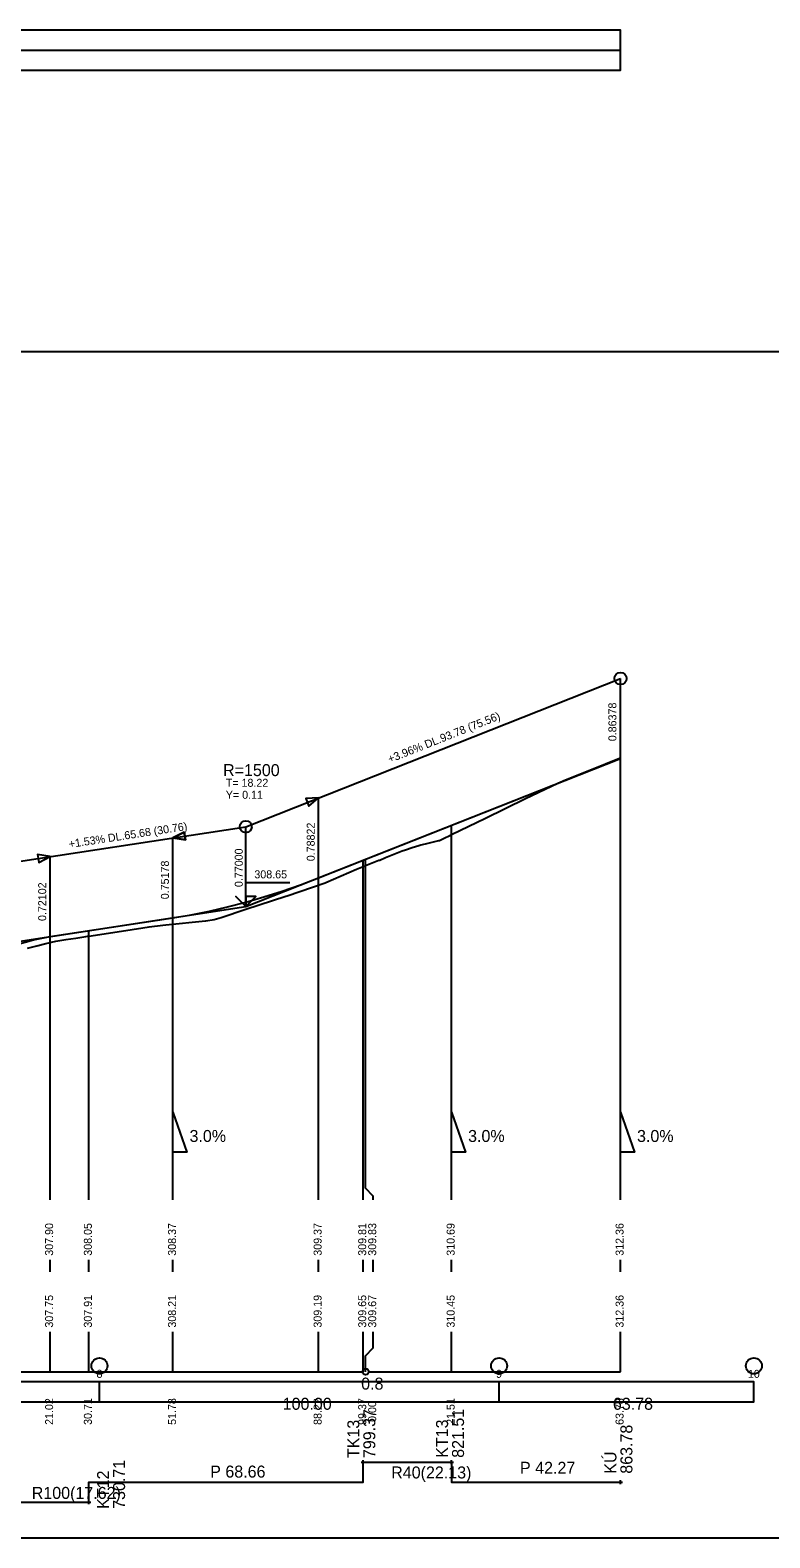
# Model space of a CAD drawing. Extents: x 999 to 1126, y 126 to 164.
# Drawn here: x 1085.78 to 1104.29, y 126.11 to 163.87 of the extents above; entities that cross this region are included whole.
import ezdxf

# ---------------------------------------------------------------- set-up
doc = ezdxf.new("R2010")
doc.units = 0
for name, color, linetype in [('KOTA', 7, 'Continuous'), ('NOVY_STAV', 7, 'Continuous'), ('NS_OBLOUK', 7, 'Continuous'), ('REZY_PO', 7, 'Continuous'), ('SESTAVY_REZU_PO', 7, 'Continuous'), ('SKLONOVE_POMERY', 7, 'Continuous'), ('SMEROVE_POMERY', 7, 'Continuous'), ('SMEROVE_POMERY_KOD', 7, 'Continuous'), ('SVK_STAT', 7, 'Continuous'), ('TABULKY', 7, 'Continuous'), ('u_pricne_rezy', 7, 'Continuous'), ('x_formát_rám', 7, 'Continuous')]:
    doc.layers.add(name, color=color, linetype=linetype)

msp = doc.modelspace()

# ---------------------------------------------------------------- linework, layer by layer
at = {"layer": 'KOTA'}
for points in [[(1091.178, 141.92), (1090.928, 142.17), (1091.178, 141.92), (1091.178, 142.52), (1092.278, 142.52)], [(1091.178, 142.17), (1091.178, 141.92), (1091.428, 142.17), (1091.178, 142.17)], [(1091.178, 141.92), (1091.428, 142.17), (1091.178, 142.17)], [(1091.178, 141.92), (1091.178, 141.92)]]:
    msp.add_lwpolyline(points, dxfattribs=at)
at = {"layer": 'NOVY_STAV'}
for points in [[(1091.178, 143.92), (1100.556, 147.632)], [(1100.556, 145.632), (1100.556, 147.632)], [(1084.178, 140.561), (1084.61, 140.916), (1091.178, 141.92), (1100.556, 145.632)], [(1084.178, 140.408), (1084.193, 140.417), (1084.61, 140.637), (1085.027, 140.823), (1085.445, 140.974), (1085.862, 141.09), (1086.28, 141.171), (1089.356, 141.642), (1089.812, 141.718), (1090.267, 141.809), (1090.723, 141.913), (1091.178, 142.031), (1091.633, 142.163), (1092.089, 142.309), (1092.544, 142.468), (1093, 142.641), (1100.556, 145.632)], [(1084.61, 142.916), (1091.178, 143.92)], [(1091.178, 141.92), (1091.178, 143.92)]]:
    msp.add_lwpolyline(points, dxfattribs=at)
for centre in [(1100.556, 147.632), (1091.178, 143.92)]:
    msp.add_circle(centre, 0.15, dxfattribs=at)
at = {"layer": 'NS_OBLOUK'}
for points in [[(1092.758, 144.438), (1093, 144.642), (1092.684, 144.624), (1092.758, 144.438)], [(1093, 142.642), (1093, 144.642)], [(1089.356, 143.642), (1089.668, 143.588), (1089.638, 143.786), (1089.356, 143.642)], [(1089.356, 141.642), (1089.356, 143.642)], [(1085.998, 143.027), (1086.28, 143.171), (1085.968, 143.225), (1085.998, 143.027)], [(1086.28, 141.171), (1086.28, 143.171)]]:
    msp.add_lwpolyline(points, dxfattribs=at)
for points in [[(1093, 144.642), (1092.684, 144.624), (1092.758, 144.438)], [(1089.356, 143.642), (1089.638, 143.786), (1089.668, 143.588)], [(1086.28, 143.171), (1085.968, 143.225), (1085.998, 143.027)]]:
    msp.add_lwpolyline(points, close=True, dxfattribs=at)
at = {"layer": 'REZY_PO'}
msp.add_lwpolyline([(1085.718, 140.879), (1085.948, 140.936), (1086.178, 140.994), (1086.427, 141.056), (1086.428, 141.056), (1086.678, 141.094), (1086.928, 141.132), (1087.178, 141.17), (1087.214, 141.176), (1087.25, 141.181), (1088.178, 141.323), (1088.763, 141.413), (1089.105, 141.454), (1089.178, 141.462), (1090.171, 141.56), (1090.178, 141.561), (1090.389, 141.593), (1090.564, 141.651), (1091.178, 141.853), (1092.178, 142.182), (1092.212, 142.193), (1093.168, 142.516), (1093.178, 142.521), (1093.945, 142.858), (1094.115, 142.924), (1094.147, 142.936), (1094.178, 142.948), (1094.345, 143.013), (1094.511, 143.08), (1094.529, 143.087), (1094.678, 143.146), (1094.845, 143.213), (1095.011, 143.28), (1095.096, 143.315), (1095.178, 143.342), (1095.345, 143.397), (1095.511, 143.451), (1095.558, 143.466), (1095.678, 143.496), (1095.845, 143.536), (1096.011, 143.575), (1096.023, 143.578), (1096.178, 143.651), (1096.253, 143.687), (1096.329, 143.723), (1097.178, 144.136), (1098.178, 144.623), (1098.985, 145.015), (1099.178, 145.093), (1100.178, 145.498), (1100.531, 145.641), (1100.556, 145.632)], dxfattribs=at)
at = {"layer": 'SESTAVY_REZU_PO'}
for points in [[(1084.253, 130.273), (1094.103, 130.273)], [(1094.253, 130.273), (1100.556, 130.273)]]:
    msp.add_lwpolyline(points, dxfattribs=at)
msp.add_circle((1094.178, 130.273), 0.075, dxfattribs=at)
at = {"layer": 'SKLONOVE_POMERY'}
for points in [[(1089.356, 135.773), (1089.356, 136.773), (1089.356, 136.773), (1089.531, 136.273), (1089.706, 135.773), (1089.356, 135.773)], [(1096.329, 135.773), (1096.329, 136.773), (1096.329, 136.773), (1096.504, 136.273), (1096.679, 135.773), (1096.329, 135.773)], [(1100.556, 135.773), (1100.556, 136.773), (1100.556, 136.773), (1100.731, 136.273), (1100.906, 135.773), (1100.556, 135.773)]]:
    msp.add_lwpolyline(points, dxfattribs=at)
at = {"layer": 'SMEROVE_POMERY'}
msp.add_lwpolyline([(1085.488, 127.01), (1087.25, 127.01), (1087.25, 127.51), (1094.115, 127.51), (1094.115, 128.01), (1096.329, 128.01), (1096.329, 127.51), (1100.556, 127.51)], dxfattribs=at)
at = {"layer": 'SMEROVE_POMERY_KOD'}
for points in [[(1094.065, 128.01), (1094.165, 128.01)], [(1094.115, 127.96), (1094.115, 128.06)], [(1096.279, 128.01), (1096.379, 128.01)], [(1096.329, 127.96), (1096.329, 128.06)], [(1100.506, 127.51), (1100.606, 127.51)], [(1100.556, 127.46), (1100.556, 127.56)], [(1087.2, 127.01), (1087.3, 127.01)], [(1087.25, 126.96), (1087.25, 127.06)]]:
    msp.add_lwpolyline(points, dxfattribs=at)
at = {"layer": 'SVK_STAT'}
for points in [[(1100.556, 134.573), (1100.556, 147.632)], [(1096.329, 134.573), (1096.329, 143.959)], [(1094.365, 134.573), (1094.365, 134.673), (1094.178, 134.873), (1094.178, 143.108)], [(1094.115, 134.573), (1094.115, 143.083)], [(1093, 134.573), (1093, 142.641)], [(1089.356, 134.573), (1089.356, 141.642)], [(1087.25, 134.573), (1087.25, 141.32)], [(1086.28, 134.573), (1086.28, 141.171)], [(1086.28, 132.773), (1086.28, 133.073)], [(1087.25, 132.773), (1087.25, 133.073)], [(1089.356, 132.773), (1089.356, 133.073)], [(1093, 132.773), (1093, 133.073)], [(1094.115, 132.773), (1094.115, 133.073)], [(1094.365, 132.773), (1094.365, 133.073)], [(1096.329, 132.773), (1096.329, 133.073)], [(1100.556, 132.773), (1100.556, 133.073)], [(1086.28, 130.273), (1086.28, 131.273)], [(1087.25, 130.273), (1087.25, 131.273)], [(1089.356, 130.273), (1089.356, 131.273)], [(1093, 130.273), (1093, 131.273)], [(1094.115, 130.273), (1094.115, 131.273)], [(1094.178, 130.273), (1094.178, 130.673), (1094.365, 130.873), (1094.365, 131.273)], [(1096.329, 130.273), (1096.329, 131.273)], [(1100.556, 130.273), (1100.556, 131.273)]]:
    msp.add_lwpolyline(points, dxfattribs=at)
at = {"layer": 'TABULKY'}
for points in [[(1014.178, 162.868), (1100.556, 162.868), (1100.556, 163.868), (1014.178, 163.868), (1014.178, 162.868)], [(1014.178, 163.368), (1100.556, 163.368)]]:
    msp.add_lwpolyline(points, dxfattribs=at)
at = {"layer": 'u_pricne_rezy'}
for points in [[(1017.517, 129.52), (1103.895, 129.52), (1103.895, 130.02), (1017.517, 130.02), (1017.517, 129.52)], [(1087.517, 129.52), (1087.517, 130.02)], [(1097.517, 129.52), (1097.517, 130.02)]]:
    msp.add_lwpolyline(points, dxfattribs=at)
for centre in [(1087.517, 130.42), (1097.517, 130.42), (1103.895, 130.42)]:
    msp.add_circle(centre, 0.2, dxfattribs=at)
at = {"layer": 'x_formát_rám'}
msp.add_lwpolyline([(999.491, 126.113), (1125.491, 126.113), (1125.491, 155.813), (999.491, 155.813)], close=True, dxfattribs=at)

# ---------------------------------------------------------------- texts
at = {"layer": 'KOTA'}
msp.add_text('308.65', height=0.2, dxfattribs=at).set_placement((1091.393, 142.628))
at = {"layer": 'NOVY_STAV'}
for s, rotation, p in [(' 0.86378', 90, (1100.453, 145.987)), ('+3.96% DL.93.78 (75.56)', 21.5951, (1094.781, 145.514)), ('+1.53% DL.65.68 (30.76)', 8.694, (1086.765, 143.386)), (' 0.77000', 90, (1091.102, 142.335))]:
    msp.add_text(s, height=0.2, rotation=rotation, dxfattribs=at).set_placement(p)
at = {"layer": 'NS_OBLOUK'}
for s, height, p in [('R=1500', 0.3, (1090.61, 145.188)), ('T= 18.22', 0.2, (1090.678, 144.92)), ('Y= 0.11', 0.2, (1090.678, 144.62))]:
    msp.add_text(s, height=height, dxfattribs=at).set_placement(p)
for s, p in [(' 0.78822', (1092.904, 142.982)), (' 0.75178', (1089.254, 142.03)), (' 0.72102', (1086.183, 141.485))]:
    msp.add_text(s, height=0.2, rotation=90, dxfattribs=at).set_placement(p)
at = {"layer": 'SESTAVY_REZU_PO'}
msp.add_text('0.8', height=0.3, dxfattribs=at).set_placement((1094.066, 129.825))
at = {"layer": 'SKLONOVE_POMERY'}
for p in [(1089.77, 136.026), (1096.742, 136.026), (1100.97, 136.026)]:
    msp.add_text('3.0%', height=0.3, dxfattribs=at).set_placement(p)
at = {"layer": 'SMEROVE_POMERY'}
for s, p in [('P 42.27', (1098.041, 127.717)), ('P 68.66', (1090.288, 127.622)), ('R40(22.13)', (1094.818, 127.6)), ('R100(17.62)', (1085.822, 127.088))]:
    msp.add_text(s, height=0.3, dxfattribs=at).set_placement(p)
at = {"layer": 'SMEROVE_POMERY_KOD'}
for s, p in [('799.37', (1094.42, 128.11)), ('821.51', (1096.64, 128.117)), ('TK13', (1094.02, 128.11)), ('KT13', (1096.24, 128.117)), ('863.78', (1100.854, 127.719)), ('730.71', (1088.157, 126.839)), ('KÚ', (1100.454, 127.719)), ('KT12', (1087.757, 126.839))]:
    msp.add_text(s, height=0.3, rotation=90, dxfattribs=at).set_placement(p)
at = {"layer": 'SVK_STAT'}
for s, p in [(' 307.90', (1086.356, 133.103)), (' 308.05', (1087.326, 133.103)), (' 308.37', (1089.433, 133.103)), (' 309.37', (1093.076, 133.103)), (' 309.81', (1094.192, 133.103)), (' 309.83', (1094.442, 133.103)), (' 310.69', (1096.405, 133.103)), (' 312.36', (1100.633, 133.103)), (' 307.75', (1086.356, 131.303)), (' 307.91', (1087.326, 131.303)), (' 308.21', (1089.433, 131.303)), (' 309.19', (1093.076, 131.303)), (' 309.65', (1094.192, 131.303)), (' 309.67', (1094.442, 131.303)), (' 310.45', (1096.405, 131.303)), (' 312.36', (1100.633, 131.303)), (' 21.02', (1086.356, 128.867)), (' 30.71', (1087.326, 128.867)), (' 51.78', (1089.433, 128.867)), (' 88.22', (1093.076, 128.867)), (' 99.37', (1094.192, 128.867)), ('  0.00', (1094.442, 128.867)), (' 21.51', (1096.405, 128.867)), (' 63.78', (1100.633, 128.867))]:
    msp.add_text(s, height=0.2, rotation=90, dxfattribs=at).set_placement(p)
at = {"layer": 'u_pricne_rezy'}
for s, height, p in [('8', 0.2, (1087.442, 130.12)), ('9', 0.2, (1097.442, 130.12)), ('10', 0.2, (1103.744, 130.12)), ('100.00', 0.3, (1092.102, 129.32)), ('63.78', 0.3, (1100.366, 129.32))]:
    msp.add_text(s, height=height, dxfattribs=at).set_placement(p)

doc.saveas('drawing.dxf')
